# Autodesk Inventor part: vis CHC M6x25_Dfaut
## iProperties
Created: 2006-03
Part Number: vis CHC M6x25_Dfaut
Document SubType Name: Modeling
Designer: Flavien MARTY
Author: Flavien MARTY
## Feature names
1. Base1
